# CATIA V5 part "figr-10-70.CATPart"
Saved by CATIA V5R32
Part number: Part1
Bounding box of the stored display mesh (mm): x -80.563 to 63.541, y -72 to 69, z -55 to 56
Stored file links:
  D:\PROJECTS\Project 2022\CATIA V5 6R 2022\Resources\Part Files\c10_catia_v5_6r2022_prt\c10_catia_v5_6r2022_prt\figr-10-70.CATPart
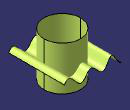
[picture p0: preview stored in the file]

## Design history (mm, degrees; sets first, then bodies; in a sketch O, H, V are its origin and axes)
Set1
  Sketch1 on xy-plane, origin (0, 0, 0), H (-1, 0, 0), V (0, -1, 0)
    circle A1 centre (0, 0) radius 45.985
  Extrude1: Element1 Sketch1, Lim1 56, Lim2 55, Direction xy-plane
  Sketch2 on zx-plane, origin (0, 0, 0), H (1, 0, 0), V (0, 0, -1)
    spline S1 through (-80.5635, 24.8913) (-73.6025, 19.8803) (-54.8525, -3.3629) (-35.1982, 19.8803) (-2.6271, -1.6506) (16.6996, 17.2854) (52.4104, -6.7877) (63.5409, 1.5862)
  Extrude2: Element1 Sketch2, Lim1 72, Lim2 69, Direction Sketch1.V
Body1 (main body)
